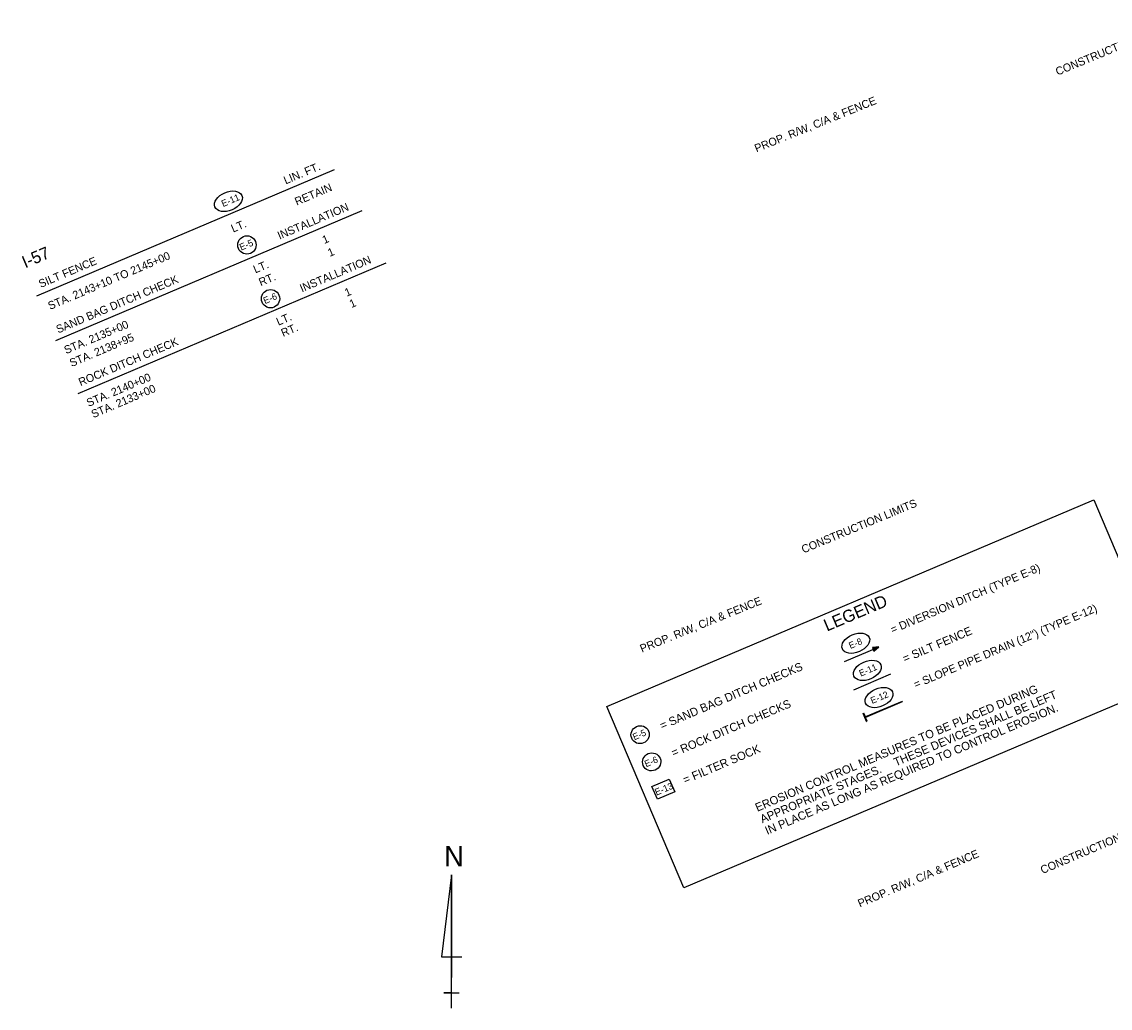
# Model space of a CAD drawing. Extents: x 1718855 to 1720684, y 766616 to 767857.
# Drawn here: x 1718855 to 1719671, y 766714 to 767454 of the extents above; entities that cross this region are included whole.
import ezdxf

# ---------------------------------------------------------------- set-up
doc = ezdxf.new("R2010")
doc.units = 0
for name, color, linetype in [('1', 7, 'Continuous'), ('44', 7, 'Continuous'), ('63', 7, 'Continuous'), ('Level 1', 7, 'Continuous'), ('Level 44', 7, 'Continuous'), ('R_Draft', 7, 'Continuous')]:
    doc.layers.add(name, color=color, linetype=linetype)

msp = doc.modelspace()

# ---------------------------------------------------------------- linework, layer by layer
at = {"layer": '1'}
for points in [[(1719293.73, 766940.43), (1719658.89, 767095.35), (1719716.65, 766959.21), (1719351.5, 766804.28)], [(1719327.64, 766880.48), (1719340.55, 766885.96), (1719344.66, 766876.29), (1719331.75, 766870.81)]]:
    msp.add_lwpolyline(points, close=True, dxfattribs=at)
for centre in [(1719023.87, 767286.66), (1719041.59, 767246.34)]:
    msp.add_circle(centre, 6.88, dxfattribs=at)
msp.add_ellipse((1719010.02, 767319.42), major_axis=(10.09, 4.28), ratio=0.638788, dxfattribs=at)
at = {"layer": '44'}
for p, q in [((1718866.27, 767248.57), (1719089.51, 767343.29)), ((1718880.55, 767214.92), (1719110.26, 767312.38)), ((1718897.35, 767175.32), (1719128.43, 767273.36))]:
    msp.add_line(p, q, dxfattribs=at)
at = {"layer": '63'}
for p, q in [((1719177.38, 766814.05), (1719169.69, 766752.51)), ((1719177.38, 766714.05), (1719177.38, 766814.05)), ((1719177.38, 766814.05), (1719177.38, 766737.13)), ((1719169.69, 766752.51), (1719185.08, 766752.51)), ((1719177.38, 766714.05), (1719177.38, 766737.13)), ((1719177.38, 766725.59), (1719171.62, 766725.59)), ((1719171.62, 766725.59), (1719183.15, 766725.59)), ((1719177.38, 766714.05), (1719177.38, 766725.59))]:
    msp.add_line(p, q, dxfattribs=at)
at = {"layer": 'Level 1'}
for p, q in [((1719497.89, 766985.14), (1719492.9, 766984.59)), ((1719492.9, 766984.59), (1719494.03, 766981.93)), ((1719496.63, 766984.91), (1719493.05, 766984.26)), ((1719496.65, 766984.82), (1719493.19, 766983.92)), ((1719496.68, 766984.73), (1719493.33, 766983.6)), ((1719493.61, 766982.93), (1719496.76, 766984.55)), ((1719493.75, 766982.6), (1719496.8, 766984.47)), ((1719493.89, 766982.26), (1719496.85, 766984.4)), ((1719494.03, 766981.93), (1719497.89, 766985.14))]:
    msp.add_line(p, q, dxfattribs=at)
msp.add_lwpolyline([(1719471.94, 766974.13), (1719496.33, 766984.48)], dxfattribs=at)
for centre, major_axis, ratio in [((1719480.49, 766987.89), (10.09, 4.28), 0.622952), ((1719489.17, 766967.49), (10.08, 4.29), 0.622952), ((1719497.96, 766947.1), (10.09, 4.28), 0.622952), ((1719318.76, 766919.27), (-6.33, -2.69), 0.97521), ((1719327.44, 766898.87), (-6.33, -2.69), 0.97521)]:
    msp.add_ellipse(centre, major_axis=major_axis, ratio=ratio, dxfattribs=at)
at = {"layer": 'Level 44'}
for p, q in [((1719515.17, 766944.27), (1719487.68, 766932.61)), ((1719515.37, 766943.81), (1719487.87, 766932.14)), ((1719515.17, 766944.27), (1719515.37, 766943.81)), ((1719486, 766935.27), (1719486.46, 766935.47)), ((1719488.63, 766929.09), (1719486, 766935.27)), ((1719487.68, 766932.61), (1719486.46, 766935.47)), ((1719489.09, 766929.28), (1719487.87, 766932.14)), ((1719488.63, 766929.09), (1719489.09, 766929.28))]:
    msp.add_line(p, q, dxfattribs=at)
msp.add_lwpolyline([(1719478.97, 766953), (1719506.68, 766964.8)], dxfattribs=at)

# ---------------------------------------------------------------- texts
at = {"layer": '1'}
for s, rotation, p in [('E-11', 22.9899, (1719006, 767315.04)), ('E-5 ', 22.9899, (1719019.57, 767282.36)), ('E-6 ', 22.9899, (1719037.45, 767242.23)), ('E-13', 22.60764, (1719331.02, 766873.54))]:
    msp.add_text(s, height=4.999, rotation=rotation, dxfattribs=at).set_placement(p)
at = {"layer": '44'}
for s, p in [('LIN. FT.', (1719052.96, 767332.03)), ('RETAIN', (1719061.28, 767316.11)), ('INSTALLATION', (1719048.34, 767290.63)), ('LT.', (1719013.55, 767295.86)), ('1', (1719081.88, 767287.34)), ('SILT FENCE      ', (1718869.25, 767254.35)), ('STA. 2143+10 TO 2145+00', (1718876.24, 767237.87)), ('INSTALLATION', (1719065.14, 767251.03)), ('1', (1719085.98, 767277.66)), ('LT.', (1719030.2, 767265.24)), ('SAND BAG DITCH CHECK', (1718882.36, 767220.21)), ('RT.', (1719034.3, 767255.57)), ('1', (1719098.68, 767247.74)), ('1', (1719102.26, 767239.29)), ('STA. 2135+00', (1718888.32, 767204.7)), ('LT.', (1719047.46, 767226.01)), ('STA. 2138+95', (1718892.43, 767195.02)), ('RT.', (1719051.04, 767217.56)), ('ROCK DITCH CHECK', (1718899.16, 767180.61)), ('STA. 2140+00', (1718905.12, 767165.1)), ('STA. 2133+00', (1718908.71, 767156.65))]:
    msp.add_text(s, height=6, rotation=22.9899, dxfattribs=at).set_placement(p)
at = {"layer": '63'}
msp.add_text('N', height=15.38, rotation=360, dxfattribs=at).set_placement((1719171.75, 766820.46))
at = {"layer": 'Level 1'}
for s, height, rotation, p in [('= DIVERSION DITCH (TYPE E-8)', 6, 22.98991, (1719508.06, 766994.97)), ('= SLOPE PIPE DRAIN (12") (TYPE E-12)', 6, 22.98991, (1719525.48, 766953.89)), ('= SILT FENCE', 6.25, 23.0479, (1719517.31, 766973.17)), ('E-8', 4.876, 22.98991, (1719476.46, 766983.53)), ('= SAND BAG DITCH CHECKS', 6.25, 23.0479, (1719335.19, 766922.87)), ('E-11 ', 4.876, 23.0479, (1719484.23, 766962.78)), ('EROSION CONTROL MEASURES TO BE PLACED DURING', 6.25, 23.0479, (1719406.68, 766861.4)), ('E-12', 4.876, 22.98991, (1719492.77, 766942.28)), ('THESE DEVICES SHALL BE LEFT', 6.25, 23.0479, (1719510.53, 766895.36)), ('= ROCK DITCH CHECKS', 6.25, 23.0479, (1719343.87, 766902.46)), ('IN PLACE AS LONG AS REQUIRED TO CONTROL EROSION.', 6.25, 23.0479, (1719414.05, 766844.09)), ('E-5 ', 4.876, 23.0479, (1719314.44, 766915.02)), ('= FILTER SOCK', 6.25, 22.98991, (1719352.49, 766882.15)), ('E-6 ', 4.876, 23.0479, (1719323.28, 766894.78)), ('APPROPRIATE STAGES. ', 6.25, 23.0479, (1719410.37, 766852.74))]:
    msp.add_text(s, height=height, rotation=rotation, dxfattribs=at).set_placement(p)
at = {"layer": 'Level 44'}
for s, rotation, p in [('I-57', 22.98991, (1718857.57, 767269.09)), ('LEGEND', 23.0479, (1719458.87, 766996.55))]:
    msp.add_text(s, height=9.143, rotation=rotation, dxfattribs=at).set_placement(p)
at = {"layer": 'R_Draft'}
for s, rotation, p in [('CONSTRUCTION LIMITS', 22.5, (1719631.82, 767413.63)), ('PROP. R/W, C/A & FENCE', 22.04919, (1719406.03, 767356.01)), ('CONSTRUCTION LIMITS', 22.5, (1719441.28, 767055.22)), ('PROP. R/W, C/A & FENCE', 22.04919, (1719320.11, 766980.74)), ('CONSTRUCTION LIMITS', 23, (1719620.52, 766814.68)), ('PROP. R/W, C/A & FENCE', 23, (1719483.55, 766789.59))]:
    msp.add_text(s, height=6, rotation=rotation, dxfattribs=at).set_placement(p)

doc.saveas('drawing.dxf')
